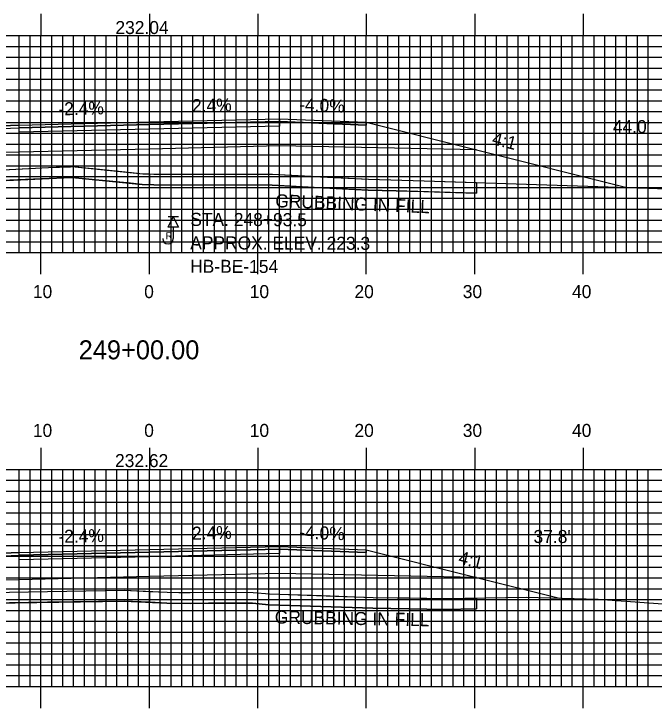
# Model space of a CAD drawing. Extents: x 1803503 to 1803847, y 442591 to 442811.
# Drawn here: x 1803656.6 to 1803715.7, y 442686.7 to 442750.7 of the extents above; entities that cross this region are included whole.
import ezdxf

# ---------------------------------------------------------------- set-up
doc = ezdxf.new("R2010")
doc.units = 0
for name, color, linetype in [('ANNOTATION', 7, 'Continuous'), ('BORING - REFUSAL', 7, 'Continuous'), ('D_Roadway_Centerline', 7, 'Continuous'), ('D_Roadway_Centerline_Text', 7, 'Continuous'), ('D_Roadway_Edge_Shoulder', 7, 'Continuous'), ('D_Roadway_Edge_TW', 7, 'Continuous'), ('D_Roadway_Pavement', 7, 'Continuous'), ('D_Roadway_SlopeLines', 7, 'Continuous'), ('D_Roadway_SubGrade', 7, 'Continuous'), ('D_Text_Standard', 7, 'Continuous'), ('GRUBBING IN FILL', 7, 'Continuous'), ('H_V ANNOTATION', 7, 'Continuous'), ('MAJOR', 7, 'Continuous'), ('MINOR', 7, 'Continuous'), ('S_Roadway_Centerline', 7, 'Continuous')]:
    doc.layers.add(name, color=color, linetype=linetype)

msp = doc.modelspace()

# ---------------------------------------------------------------- linework, layer by layer
at = {"layer": 'BORING - REFUSAL'}
for p, q in [((1803671.821, 442731.965), (1803670.861, 442731.965)), ((1803671.341, 442731.006), (1803671.341, 442729.947))]:
    msp.add_line(p, q, dxfattribs=at)
msp.add_lwpolyline([(1803671.341, 442731.965), (1803671.821, 442731.006), (1803670.861, 442731.006)], close=True, dxfattribs=at)
msp.add_arc((1803670.856, 442729.947), 0.485, 180, 0, dxfattribs=at)
at = {"layer": 'D_Roadway_Centerline'}
for points in [[(1803633.162, 442736.104), (1803637.141, 442737.098), (1803638.967, 442737.555), (1803649.141, 442740.098), (1803657.141, 442740.418), (1803669.141, 442740.706), (1803681.141, 442740.994), (1803689.141, 442740.674), (1803699.315, 442738.131), (1803713.175, 442734.666)], [(1803632.797, 442697.673), (1803633.34, 442697.641), (1803633.882, 442697.541), (1803634.424, 442697.372), (1803634.967, 442697.135), (1803638.967, 442698.135), (1803649.141, 442700.678), (1803657.141, 442700.998), (1803669.141, 442701.286), (1803681.141, 442701.574), (1803689.141, 442701.254), (1803699.315, 442698.711), (1803706.969, 442696.797)]]:
    msp.add_lwpolyline(points, dxfattribs=at)
at = {"layer": 'D_Roadway_Edge_Shoulder'}
for points in [[(1803681.141, 442740.994), (1803689.141, 442740.674), (1803689.141, 442740.424), (1803681.141, 442740.744)], [(1803657.141, 442740.418), (1803649.141, 442740.098), (1803649.141, 442739.848), (1803657.141, 442740.168)], [(1803681.141, 442701.574), (1803689.141, 442701.254), (1803689.141, 442701.004), (1803681.141, 442701.324)], [(1803657.141, 442700.998), (1803649.141, 442700.678), (1803649.141, 442700.428), (1803657.141, 442700.748)]]:
    msp.add_lwpolyline(points, close=True, dxfattribs=at)
at = {"layer": 'D_Roadway_Edge_TW'}
for points in [[(1803657.141, 442740.168), (1803657.141, 442740.418), (1803669.141, 442740.706), (1803681.141, 442740.994), (1803681.141, 442740.744), (1803669.141, 442740.456)], [(1803657.141, 442700.748), (1803657.141, 442700.998), (1803669.141, 442701.286), (1803681.141, 442701.574), (1803681.141, 442701.324), (1803669.141, 442701.036)]]:
    msp.add_lwpolyline(points, close=True, dxfattribs=at)
at = {"layer": 'D_Roadway_Pavement'}
for points in [[(1803657.141, 442739.752), (1803657.141, 442740.168), (1803669.141, 442740.456), (1803681.141, 442740.744), (1803681.141, 442740.328), (1803669.141, 442740.04)], [(1803657.141, 442700.332), (1803657.141, 442700.748), (1803669.141, 442701.036), (1803681.141, 442701.324), (1803681.141, 442700.908), (1803669.141, 442700.62)]]:
    msp.add_lwpolyline(points, close=True, dxfattribs=at)
at = {"layer": 'D_Roadway_SlopeLines'}
for points in [[(1803689.141, 442740.674), (1803699.315, 442738.131), (1803713.175, 442734.666)], [(1803689.141, 442701.254), (1803699.315, 442698.711), (1803706.969, 442696.797)]]:
    msp.add_lwpolyline(points, dxfattribs=at)
at = {"layer": 'D_Roadway_SubGrade'}
for points in [[(1803657.141, 442737.918), (1803638.967, 442737.555), (1803649.141, 442740.098), (1803649.141, 442739.848), (1803657.141, 442740.168), (1803669.141, 442740.456), (1803681.141, 442740.744), (1803689.141, 442740.424), (1803689.141, 442740.674), (1803699.315, 442738.131), (1803681.141, 442738.494), (1803669.141, 442738.206)], [(1803657.141, 442698.498), (1803638.967, 442698.135), (1803649.141, 442700.678), (1803649.141, 442700.428), (1803657.141, 442700.748), (1803669.141, 442701.036), (1803681.141, 442701.324), (1803689.141, 442701.004), (1803689.141, 442701.254), (1803699.315, 442698.711), (1803681.141, 442699.074), (1803669.141, 442698.786)]]:
    msp.add_lwpolyline(points, close=True, dxfattribs=at)
at = {"layer": 'GRUBBING IN FILL'}
for p, q in [((1803699.315, 442735.13), (1803699.315, 442734.13)), ((1803699.315, 442735.13), (1803699.315, 442734.13)), ((1803699.315, 442696.812), (1803699.315, 442695.812)), ((1803699.315, 442696.812), (1803699.315, 442695.812))]:
    msp.add_line(p, q, dxfattribs=at)
for points in [[(1803638.967, 442736.125), (1803640.1, 442736.129), (1803647.171, 442736.154), (1803649.883, 442736.153), (1803652.596, 442736.152), (1803656.22, 442736.322), (1803659.844, 442736.493), (1803662, 442736.585), (1803664.222, 442736.368), (1803667.485, 442736.044), (1803668.526, 442735.936), (1803669.141, 442735.915), (1803669.141, 442734.915), (1803668.457, 442734.938), (1803667.401, 442735.047), (1803664.176, 442735.368), (1803662.007, 442735.579), (1803659.886, 442735.494), (1803656.253, 442735.323), (1803652.62, 442735.152), (1803649.896, 442735.153), (1803647.172, 442735.154), (1803643.069, 442735.139), (1803638.967, 442735.125)], [(1803638.967, 442736.125), (1803640.1, 442736.129), (1803647.171, 442736.154), (1803649.883, 442736.153), (1803652.596, 442736.152), (1803656.22, 442736.322), (1803659.844, 442736.493), (1803662, 442736.585), (1803664.222, 442736.368), (1803667.485, 442736.044), (1803668.526, 442735.936), (1803669.141, 442735.915), (1803669.141, 442734.915), (1803668.457, 442734.938), (1803667.401, 442735.047), (1803664.176, 442735.368), (1803662.007, 442735.579), (1803659.886, 442735.494), (1803656.253, 442735.323), (1803652.62, 442735.152), (1803649.896, 442735.153), (1803647.172, 442735.154), (1803643.069, 442735.139), (1803638.967, 442735.125)], [(1803669.141, 442735.915), (1803675.028, 442735.888), (1803680.499, 442735.876), (1803684.923, 442735.646), (1803689.346, 442735.416), (1803694.483, 442735.291), (1803699.315, 442735.13), (1803699.315, 442734.13), (1803696.885, 442734.21), (1803691.881, 442734.354), (1803689.308, 442734.416), (1803684.89, 442734.646), (1803680.472, 442734.876), (1803675.006, 442734.888), (1803669.539, 442734.901), (1803669.141, 442734.915)], [(1803669.141, 442735.915), (1803675.028, 442735.888), (1803680.499, 442735.876), (1803684.923, 442735.646), (1803689.346, 442735.416), (1803694.483, 442735.291), (1803699.315, 442735.13), (1803699.315, 442734.13), (1803696.885, 442734.21), (1803691.881, 442734.354), (1803689.308, 442734.416), (1803684.89, 442734.646), (1803680.472, 442734.876), (1803675.006, 442734.888), (1803669.539, 442734.901), (1803669.141, 442734.915)], [(1803638.967, 442697.625), (1803642.38, 442697.456), (1803647.158, 442697.219), (1803648.422, 442697.153), (1803649.687, 442697.087), (1803651.177, 442697.19), (1803652.667, 442697.293), (1803659.74, 442697.415), (1803666.814, 442697.536), (1803669.141, 442697.425), (1803669.141, 442696.424), (1803666.798, 442696.536), (1803659.754, 442696.415), (1803652.71, 442696.294), (1803651.203, 442696.189), (1803649.695, 442696.085), (1803648.401, 442696.153), (1803643.037, 442696.422), (1803638.967, 442696.624)], [(1803638.967, 442697.625), (1803642.38, 442697.456), (1803647.158, 442697.219), (1803648.422, 442697.153), (1803649.687, 442697.087), (1803651.177, 442697.19), (1803652.667, 442697.293), (1803659.74, 442697.415), (1803666.814, 442697.536), (1803669.141, 442697.425), (1803669.141, 442696.424), (1803666.798, 442696.536), (1803659.754, 442696.415), (1803652.71, 442696.294), (1803651.203, 442696.189), (1803649.695, 442696.085), (1803648.401, 442696.153), (1803643.037, 442696.422), (1803638.967, 442696.624)], [(1803669.141, 442697.425), (1803670.785, 442697.346), (1803671.843, 442697.326), (1803672.9, 442697.306), (1803676.277, 442697.344), (1803678.703, 442697.329), (1803680.222, 442697.196), (1803685, 442697.036), (1803689.778, 442696.875), (1803693.081, 442696.82), (1803696.384, 442696.765), (1803699.315, 442696.812), (1803699.315, 442695.812), (1803697.85, 442695.788), (1803696.384, 442695.764), (1803693.068, 442695.82), (1803689.753, 442695.875), (1803684.957, 442696.037), (1803680.162, 442696.198), (1803678.656, 442696.329), (1803674.587, 442696.325), (1803672.896, 442696.306), (1803670.752, 442696.347), (1803669.141, 442696.424)], [(1803669.141, 442697.425), (1803670.785, 442697.346), (1803671.843, 442697.326), (1803672.9, 442697.306), (1803676.277, 442697.344), (1803678.703, 442697.329), (1803680.222, 442697.196), (1803685, 442697.036), (1803689.778, 442696.875), (1803693.081, 442696.82), (1803696.384, 442696.765), (1803699.315, 442696.812), (1803699.315, 442695.812), (1803697.85, 442695.788), (1803696.384, 442695.764), (1803693.068, 442695.82), (1803689.753, 442695.875), (1803684.957, 442696.037), (1803680.162, 442696.198), (1803678.656, 442696.329), (1803674.587, 442696.325), (1803672.896, 442696.306), (1803670.752, 442696.347), (1803669.141, 442696.424)]]:
    msp.add_lwpolyline(points, close=True, dxfattribs=at)
for points in [[(1803638.967, 442735.125), (1803647.172, 442735.154), (1803652.62, 442735.152), (1803659.886, 442735.494), (1803661.922, 442735.57), (1803662.007, 442735.579), (1803666.345, 442735.157), (1803668.457, 442734.938), (1803669.539, 442734.901), (1803680.472, 442734.876), (1803689.308, 442734.416), (1803694.454, 442734.291), (1803699.315, 442734.13)], [(1803638.967, 442735.125), (1803647.172, 442735.154), (1803652.62, 442735.152), (1803659.886, 442735.494), (1803661.922, 442735.57), (1803662.007, 442735.579), (1803666.345, 442735.157), (1803668.457, 442734.938), (1803669.539, 442734.901), (1803680.472, 442734.876), (1803689.308, 442734.416), (1803694.454, 442734.291), (1803699.315, 442734.13)], [(1803638.967, 442696.624), (1803647.107, 442696.22), (1803649.695, 442696.085), (1803652.71, 442696.294), (1803666.798, 442696.536), (1803670.752, 442696.347), (1803672.896, 442696.306), (1803676.279, 442696.343), (1803678.656, 442696.329), (1803680.162, 442696.198), (1803689.753, 442695.875), (1803696.384, 442695.764), (1803699.315, 442695.812)], [(1803638.967, 442696.624), (1803647.107, 442696.22), (1803649.695, 442696.085), (1803652.71, 442696.294), (1803666.798, 442696.536), (1803670.752, 442696.347), (1803672.896, 442696.306), (1803676.279, 442696.343), (1803678.656, 442696.329), (1803680.162, 442696.198), (1803689.753, 442695.875), (1803696.384, 442695.764), (1803699.315, 442695.812)]]:
    msp.add_lwpolyline(points, dxfattribs=at)
at = {"layer": 'MAJOR'}
for p, q in [((1803659.141, 442750.669), (1803659.141, 442748.665)), ((1803669.141, 442750.669), (1803669.141, 442748.665)), ((1803679.141, 442750.669), (1803679.141, 442748.665)), ((1803689.141, 442750.669), (1803689.141, 442748.665)), ((1803699.141, 442750.669), (1803699.141, 442748.665)), ((1803709.141, 442750.669), (1803709.141, 442748.665)), ((1803529.141, 442748.665), (1803809.141, 442748.665)), ((1803529.141, 442748.665), (1803809.141, 442748.665)), ((1803659.141, 442728.665), (1803659.141, 442748.665)), ((1803669.141, 442728.665), (1803669.141, 442748.665)), ((1803679.141, 442728.665), (1803679.141, 442748.665)), ((1803689.141, 442728.665), (1803689.141, 442748.665)), ((1803699.141, 442728.665), (1803699.141, 442748.665)), ((1803709.141, 442728.665), (1803709.141, 442748.665)), ((1803529.141, 442743.665), (1803809.141, 442743.665)), ((1803529.141, 442738.665), (1803809.141, 442738.665)), ((1803529.141, 442733.665), (1803809.141, 442733.665)), ((1803529.141, 442728.665), (1803809.141, 442728.665)), ((1803529.141, 442728.665), (1803809.141, 442728.665)), ((1803659.141, 442726.661), (1803659.141, 442728.665)), ((1803669.141, 442726.661), (1803669.141, 442728.665)), ((1803679.141, 442726.661), (1803679.141, 442728.665)), ((1803689.141, 442726.661), (1803689.141, 442728.665)), ((1803699.141, 442726.661), (1803699.141, 442728.665)), ((1803709.141, 442726.661), (1803709.141, 442728.665)), ((1803659.141, 442710.669), (1803659.141, 442708.665)), ((1803669.141, 442710.669), (1803669.141, 442708.665)), ((1803679.141, 442710.669), (1803679.141, 442708.665)), ((1803689.141, 442710.669), (1803689.141, 442708.665)), ((1803699.141, 442710.669), (1803699.141, 442708.665)), ((1803709.141, 442710.669), (1803709.141, 442708.665)), ((1803529.141, 442708.665), (1803809.141, 442708.665)), ((1803529.141, 442708.665), (1803809.141, 442708.665)), ((1803659.141, 442688.665), (1803659.141, 442708.665)), ((1803669.141, 442688.665), (1803669.141, 442708.665)), ((1803679.141, 442688.665), (1803679.141, 442708.665)), ((1803689.141, 442688.665), (1803689.141, 442708.665)), ((1803699.141, 442688.665), (1803699.141, 442708.665)), ((1803709.141, 442688.665), (1803709.141, 442708.665)), ((1803529.141, 442703.665), (1803809.141, 442703.665)), ((1803529.141, 442698.665), (1803809.141, 442698.665)), ((1803529.141, 442693.665), (1803809.141, 442693.665)), ((1803529.141, 442688.665), (1803809.141, 442688.665)), ((1803529.141, 442688.665), (1803809.141, 442688.665)), ((1803659.141, 442686.661), (1803659.141, 442688.665)), ((1803669.141, 442686.661), (1803669.141, 442688.665)), ((1803679.141, 442686.661), (1803679.141, 442688.665)), ((1803689.141, 442686.661), (1803689.141, 442688.665)), ((1803699.141, 442686.661), (1803699.141, 442688.665)), ((1803709.141, 442686.661), (1803709.141, 442688.665))]:
    msp.add_line(p, q, dxfattribs=at)
at = {"layer": 'MINOR'}
for p, q in [((1803657.141, 442728.665), (1803657.141, 442748.665)), ((1803658.141, 442728.665), (1803658.141, 442748.665)), ((1803660.141, 442728.665), (1803660.141, 442748.665)), ((1803661.141, 442728.665), (1803661.141, 442748.665)), ((1803662.141, 442728.665), (1803662.141, 442748.665)), ((1803663.141, 442728.665), (1803663.141, 442748.665)), ((1803664.141, 442728.665), (1803664.141, 442748.665)), ((1803665.141, 442728.665), (1803665.141, 442748.665)), ((1803666.141, 442728.665), (1803666.141, 442748.665)), ((1803667.141, 442728.665), (1803667.141, 442748.665)), ((1803668.141, 442728.665), (1803668.141, 442748.665)), ((1803670.141, 442728.665), (1803670.141, 442748.665)), ((1803671.141, 442728.665), (1803671.141, 442748.665)), ((1803672.141, 442728.665), (1803672.141, 442748.665)), ((1803673.141, 442728.665), (1803673.141, 442748.665)), ((1803674.141, 442728.665), (1803674.141, 442748.665)), ((1803675.141, 442728.665), (1803675.141, 442748.665)), ((1803676.141, 442728.665), (1803676.141, 442748.665)), ((1803677.141, 442728.665), (1803677.141, 442748.665)), ((1803678.141, 442728.665), (1803678.141, 442748.665)), ((1803680.141, 442728.665), (1803680.141, 442748.665)), ((1803681.141, 442728.665), (1803681.141, 442748.665)), ((1803682.141, 442728.665), (1803682.141, 442748.665)), ((1803683.141, 442728.665), (1803683.141, 442748.665)), ((1803684.141, 442728.665), (1803684.141, 442748.665)), ((1803685.141, 442728.665), (1803685.141, 442748.665)), ((1803686.141, 442728.665), (1803686.141, 442748.665)), ((1803687.141, 442728.665), (1803687.141, 442748.665)), ((1803688.141, 442728.665), (1803688.141, 442748.665)), ((1803690.141, 442728.665), (1803690.141, 442748.665)), ((1803691.141, 442728.665), (1803691.141, 442748.665)), ((1803692.141, 442728.665), (1803692.141, 442748.665)), ((1803693.141, 442728.665), (1803693.141, 442748.665)), ((1803694.141, 442728.665), (1803694.141, 442748.665)), ((1803695.141, 442728.665), (1803695.141, 442748.665)), ((1803696.141, 442728.665), (1803696.141, 442748.665)), ((1803697.141, 442728.665), (1803697.141, 442748.665)), ((1803698.141, 442728.665), (1803698.141, 442748.665)), ((1803700.141, 442728.665), (1803700.141, 442748.665)), ((1803701.141, 442728.665), (1803701.141, 442748.665)), ((1803702.141, 442728.665), (1803702.141, 442748.665)), ((1803703.141, 442728.665), (1803703.141, 442748.665)), ((1803704.141, 442728.665), (1803704.141, 442748.665)), ((1803705.141, 442728.665), (1803705.141, 442748.665)), ((1803706.141, 442728.665), (1803706.141, 442748.665)), ((1803707.141, 442728.665), (1803707.141, 442748.665)), ((1803708.141, 442728.665), (1803708.141, 442748.665)), ((1803710.141, 442728.665), (1803710.141, 442748.665)), ((1803711.141, 442728.665), (1803711.141, 442748.665)), ((1803712.141, 442728.665), (1803712.141, 442748.665)), ((1803713.141, 442728.665), (1803713.141, 442748.665)), ((1803714.141, 442728.665), (1803714.141, 442748.665)), ((1803715.141, 442728.665), (1803715.141, 442748.665)), ((1803529.141, 442747.665), (1803809.141, 442747.665)), ((1803529.141, 442746.665), (1803809.141, 442746.665)), ((1803529.141, 442745.665), (1803809.141, 442745.665)), ((1803529.141, 442744.665), (1803809.141, 442744.665)), ((1803529.141, 442742.665), (1803809.141, 442742.665)), ((1803529.141, 442741.665), (1803809.141, 442741.665)), ((1803529.141, 442740.665), (1803809.141, 442740.665)), ((1803529.141, 442739.665), (1803809.141, 442739.665)), ((1803529.141, 442737.665), (1803809.141, 442737.665)), ((1803529.141, 442736.665), (1803809.141, 442736.665)), ((1803529.141, 442735.665), (1803809.141, 442735.665)), ((1803529.141, 442734.665), (1803809.141, 442734.665)), ((1803529.141, 442732.665), (1803809.141, 442732.665)), ((1803529.141, 442731.665), (1803809.141, 442731.665)), ((1803529.141, 442730.665), (1803809.141, 442730.665)), ((1803529.141, 442729.665), (1803809.141, 442729.665)), ((1803657.141, 442688.665), (1803657.141, 442708.665)), ((1803658.141, 442688.665), (1803658.141, 442708.665)), ((1803660.141, 442688.665), (1803660.141, 442708.665)), ((1803661.141, 442688.665), (1803661.141, 442708.665)), ((1803662.141, 442688.665), (1803662.141, 442708.665)), ((1803663.141, 442688.665), (1803663.141, 442708.665)), ((1803664.141, 442688.665), (1803664.141, 442708.665)), ((1803665.141, 442688.665), (1803665.141, 442708.665)), ((1803666.141, 442688.665), (1803666.141, 442708.665)), ((1803667.141, 442688.665), (1803667.141, 442708.665)), ((1803668.141, 442688.665), (1803668.141, 442708.665)), ((1803670.141, 442688.665), (1803670.141, 442708.665)), ((1803671.141, 442688.665), (1803671.141, 442708.665)), ((1803672.141, 442688.665), (1803672.141, 442708.665)), ((1803673.141, 442688.665), (1803673.141, 442708.665)), ((1803674.141, 442688.665), (1803674.141, 442708.665)), ((1803675.141, 442688.665), (1803675.141, 442708.665)), ((1803676.141, 442688.665), (1803676.141, 442708.665)), ((1803677.141, 442688.665), (1803677.141, 442708.665)), ((1803678.141, 442688.665), (1803678.141, 442708.665)), ((1803680.141, 442688.665), (1803680.141, 442708.665)), ((1803681.141, 442688.665), (1803681.141, 442708.665)), ((1803682.141, 442688.665), (1803682.141, 442708.665)), ((1803683.141, 442688.665), (1803683.141, 442708.665)), ((1803684.141, 442688.665), (1803684.141, 442708.665)), ((1803685.141, 442688.665), (1803685.141, 442708.665)), ((1803686.141, 442688.665), (1803686.141, 442708.665)), ((1803687.141, 442688.665), (1803687.141, 442708.665)), ((1803688.141, 442688.665), (1803688.141, 442708.665)), ((1803690.141, 442688.665), (1803690.141, 442708.665)), ((1803691.141, 442688.665), (1803691.141, 442708.665)), ((1803692.141, 442688.665), (1803692.141, 442708.665)), ((1803693.141, 442688.665), (1803693.141, 442708.665)), ((1803694.141, 442688.665), (1803694.141, 442708.665)), ((1803695.141, 442688.665), (1803695.141, 442708.665)), ((1803696.141, 442688.665), (1803696.141, 442708.665)), ((1803697.141, 442688.665), (1803697.141, 442708.665)), ((1803698.141, 442688.665), (1803698.141, 442708.665)), ((1803700.141, 442688.665), (1803700.141, 442708.665)), ((1803701.141, 442688.665), (1803701.141, 442708.665)), ((1803702.141, 442688.665), (1803702.141, 442708.665)), ((1803703.141, 442688.665), (1803703.141, 442708.665)), ((1803704.141, 442688.665), (1803704.141, 442708.665)), ((1803705.141, 442688.665), (1803705.141, 442708.665)), ((1803706.141, 442688.665), (1803706.141, 442708.665)), ((1803707.141, 442688.665), (1803707.141, 442708.665)), ((1803708.141, 442688.665), (1803708.141, 442708.665)), ((1803710.141, 442688.665), (1803710.141, 442708.665)), ((1803711.141, 442688.665), (1803711.141, 442708.665)), ((1803712.141, 442688.665), (1803712.141, 442708.665)), ((1803713.141, 442688.665), (1803713.141, 442708.665)), ((1803714.141, 442688.665), (1803714.141, 442708.665)), ((1803715.141, 442688.665), (1803715.141, 442708.665)), ((1803529.141, 442707.665), (1803809.141, 442707.665)), ((1803529.141, 442706.665), (1803809.141, 442706.665)), ((1803529.141, 442705.665), (1803809.141, 442705.665)), ((1803529.141, 442704.665), (1803809.141, 442704.665)), ((1803529.141, 442702.665), (1803809.141, 442702.665)), ((1803529.141, 442701.665), (1803809.141, 442701.665)), ((1803529.141, 442700.665), (1803809.141, 442700.665)), ((1803529.141, 442699.665), (1803809.141, 442699.665)), ((1803529.141, 442697.665), (1803809.141, 442697.665)), ((1803529.141, 442696.665), (1803809.141, 442696.665)), ((1803529.141, 442695.665), (1803809.141, 442695.665)), ((1803529.141, 442694.665), (1803809.141, 442694.665)), ((1803529.141, 442692.665), (1803809.141, 442692.665)), ((1803529.141, 442691.665), (1803809.141, 442691.665)), ((1803529.141, 442690.665), (1803809.141, 442690.665)), ((1803529.141, 442689.665), (1803809.141, 442689.665))]:
    msp.add_line(p, q, dxfattribs=at)
at = {"layer": 'S_Roadway_Centerline'}
for points in [[(1803602.328, 442736.835), (1803610.211, 442736.538), (1803623.544, 442736.276), (1803633.029, 442736.103), (1803647.171, 442736.154), (1803652.596, 442736.152), (1803659.844, 442736.493), (1803661.848, 442736.568), (1803662, 442736.585), (1803666.445, 442736.152), (1803668.526, 442735.936), (1803669.557, 442735.901), (1803680.499, 442735.876), (1803689.346, 442735.416), (1803694.483, 442735.291), (1803711.435, 442734.727), (1803719.653, 442734.436)], [(1803603.953, 442698.023), (1803617.751, 442697.563), (1803625.398, 442697.642), (1803637.603, 442697.693), (1803647.158, 442697.219), (1803649.687, 442697.087), (1803652.667, 442697.293), (1803666.814, 442697.536), (1803670.785, 442697.346), (1803672.9, 442697.306), (1803676.277, 442697.344), (1803678.703, 442697.329), (1803680.222, 442697.196), (1803689.778, 442696.875), (1803696.384, 442696.765), (1803703.887, 442696.887), (1803710.51, 442696.694), (1803718.608, 442696.121)]]:
    msp.add_lwpolyline(points, dxfattribs=at)

# ---------------------------------------------------------------- texts
at = {"layer": 'ANNOTATION'}
for s, rotation, p in [('2.4%', 1.37483, (1803673.082, 442741.601)), ('-4.0%', 357.70939, (1803682.933, 442741.724)), ('-2.4%', 1.37483, (1803660.761, 442741.306)), ('4:1', 345.96376, (1803700.664, 442738.655)), ('-2.4%', 1.37483, (1803660.761, 442701.886)), ('2.4%', 1.37483, (1803673.082, 442702.182)), ('-4.0%', 357.70939, (1803682.933, 442702.304)), ('4:1', 345.96376, (1803697.561, 442700.011))]:
    msp.add_text(s, height=1.2, rotation=rotation, dxfattribs=at).set_placement(p)
at = {"layer": 'BORING - REFUSAL'}
for s, p in [('STA. 248+93.5', (1803672.91, 442731.125)), ('APPROX. ELEV. 223.3', (1803672.903, 442728.965)), ('HB-BE-154', (1803672.896, 442726.805))]:
    msp.add_text(s, height=1.2, rotation=359.81416, dxfattribs=at).set_placement(p)
msp.add_text('R', height=0.64, dxfattribs=at).set_placement((1803670.632, 442729.891))
at = {"layer": 'D_Roadway_Centerline'}
for s, p in [('C', (1803669.136, 442740.706)), ('L', (1803669.141, 442740.699)), ('C', (1803669.136, 442701.286)), ('L', (1803669.141, 442701.279))]:
    msp.add_text(s, height=0.0146, dxfattribs=at).set_placement(p)
at = {"layer": 'D_Roadway_Centerline_Text'}
for s, p in [('232.04', (1803666.005, 442748.811)), ('232.62', (1803665.968, 442708.88))]:
    msp.add_text(s, height=1.2, dxfattribs=at).set_placement(p)
at = {"layer": 'D_Text_Standard'}
for s, p in [("44.0'", (1803711.879, 442739.673)), ("37.8'", (1803704.565, 442701.884))]:
    msp.add_text(s, height=1.2, dxfattribs=at).set_placement(p)
at = {"layer": 'GRUBBING IN FILL'}
for rotation, p in [(357.69644, (1803680.729, 442732.853)), (358.94214, (1803680.695, 442694.467))]:
    msp.add_text('GRUBBING IN FILL', height=1.2, rotation=rotation, dxfattribs=at).set_placement(p)
at = {"layer": 'H_V ANNOTATION'}
for s, height, p in [('10', 1.2, (1803658.392, 442724.465)), ('0', 1.2, (1803668.659, 442724.465)), ('10', 1.2, (1803678.392, 442724.465)), ('20', 1.2, (1803688.049, 442724.465)), ('30', 1.2, (1803698.038, 442724.465)), ('40', 1.2, (1803708.113, 442724.465)), ('249+00.00', 1.75, (1803662.618, 442718.821)), ('10', 1.2, (1803658.392, 442711.665)), ('0', 1.2, (1803668.659, 442711.665)), ('10', 1.2, (1803678.392, 442711.665)), ('20', 1.2, (1803688.049, 442711.665)), ('30', 1.2, (1803698.038, 442711.665)), ('40', 1.2, (1803708.113, 442711.665))]:
    msp.add_text(s, height=height, dxfattribs=at).set_placement(p)

doc.saveas('drawing.dxf')
